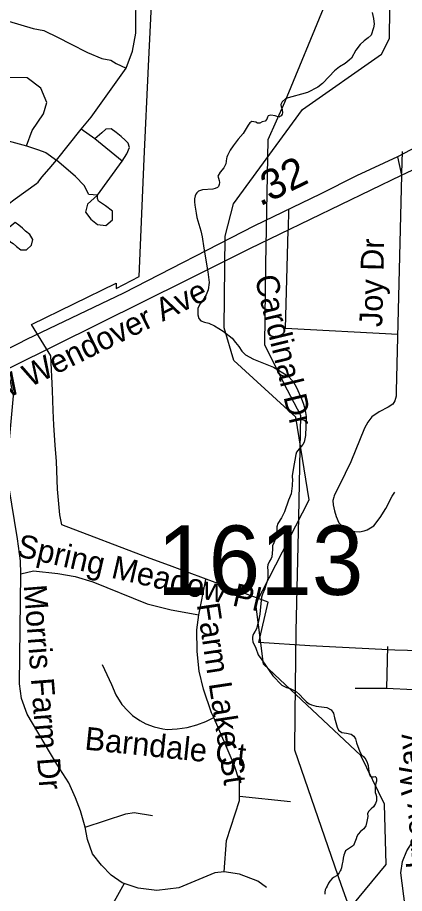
# Model space of a CAD drawing. Extents: x 1662474 to 1856135, y 779280 to 917889.
# Drawn here: x 1722010 to 1723616, y 832525 to 836159 of the extents above; entities that cross this region are included whole.
import ezdxf

# ---------------------------------------------------------------- set-up
doc = ezdxf.new("R2010")
doc.units = 0
for name, color, linetype in [('Cogo Default Point CELL', 7, 'Continuous'), ('Exist Boundary Political City Limit New', 7, 'Continuous'), ('Exist Hydrographic Creek Single Shore', 7, 'Continuous'), ('Exist Hydrographic Misc Water Feature', 7, 'Continuous'), ('Exist Road Non-System Type 51', 7, 'Continuous'), ('Exist Road Non-System Type 51 Label', 7, 'Continuous'), ('Exist Road Secondary Type 51 Attributed', 7, 'Continuous'), ('Exist Road Secondary Type 51 Divided Attributed', 7, 'Continuous'), ('Exist Road Secondary Type 51 Label', 7, 'Continuous'), ('Exist Utilities Electrical Transmission Line', 7, 'Continuous'), ('Map Preparation Boundary City Limit Buffer Line', 7, 'Continuous'), ('Prop DGN Element Guardrail', 7, 'Continuous')]:
    doc.layers.add(name, color=color, linetype=linetype)

msp = doc.modelspace()

# ---------------------------------------------------------------- linework, layer by layer
at = {"layer": 'Exist Boundary Political City Limit New'}
msp.add_lwpolyline([(1723786.9, 833529), (1723576.1, 833534.5), (1723223.9, 833552.5), (1723012.1, 833566.1), (1723050.6, 833733.9), (1722927.1, 833779.1), (1722781.8, 833832.9), (1722722.5, 833854.9), (1722652.1, 833880.9), (1722548.9, 833919.3), (1722193.4, 834054.1), (1722185.1, 834095.9), (1722176, 834201.7), (1722172, 834316.5), (1722165.9, 834384.5), (1722160.9, 834468.2), (1722158.5, 834528.1), (1722155.4, 834612.1), (1722148.5, 834756.2), (1722067.8, 834885.8), (1722418.8, 835056.8), (1722419.8, 835035.6), (1722515.2, 835085.2), (1722535.9, 835573.3), (1722554.2, 835957.6), (1722563.6, 836155.2), (1722573.2, 836360.9)], dxfattribs=at)
at = {"layer": 'Exist Hydrographic Creek Single Shore'}
for points in [[(1723482.5, 836180.6), (1723488.2, 836154.7), (1723490.4, 836131.1), (1723487.8, 836116.9), (1723478, 836085.6), (1723465.4, 836075.4), (1723449.1, 836062.2), (1723432.6, 836047.8), (1723414.2, 836023.9), (1723396.4, 835990.6), (1723387.2, 835981.9), (1723369.9, 835968.3), (1723346.5, 835954.1), (1723326, 835937.9), (1723303.5, 835914.5), (1723275.9, 835885.6), (1723256, 835869.6), (1723214, 835847.6), (1723124, 835823.7), (1723108.2, 835809.2), (1723102.4, 835798.5), (1723104.5, 835789.3), (1723107.1, 835783.6), (1723109, 835775.7), (1723110.2, 835764.4), (1723108, 835757.8), (1723103.8, 835751), (1723094.2, 835746), (1723079.4, 835751.5), (1723061, 835753.9), (1723050.8, 835750.8), (1723047.6, 835746), (1723045.2, 835737.3), (1723038.1, 835729.8), (1723025, 835726.1), (1723016.4, 835720.6), (1723006.1, 835721.1), (1722999, 835724.5), (1722982, 835728.4), (1722974.4, 835722.6), (1722967, 835712.4), (1722946.2, 835678.6), (1722925.5, 835654.7), (1722905, 835626.6), (1722892.8, 835609.2), (1722881.1, 835586.7), (1722878.8, 835580.1), (1722878, 835573.8), (1722875.1, 835551.8), (1722866.8, 835535.5), (1722850.8, 835517.1), (1722841.8, 835501.1), (1722843.6, 835492.8), (1722847.6, 835482.5), (1722848.4, 835474.9), (1722847.4, 835467), (1722843.9, 835457.8), (1722839.8, 835453.9), (1722830.8, 835449.2), (1722820, 835446.8), (1722777.5, 835443.6), (1722760.5, 835438.7), (1722754.6, 835432.1), (1722750.5, 835426.1), (1722747.9, 835419.8), (1722744.4, 835406.4), (1722743.9, 835394.1), (1722745.8, 835380.6), (1722748.1, 835364.4), (1722751, 835347.1), (1722754.6, 835329.2), (1722771.2, 835274.6), (1722775.9, 835248.9), (1722783.5, 835202.4), (1722799.8, 835104.6), (1722806.1, 835060.4), (1722801.1, 835029.8), (1722793, 835009), (1722780.1, 834988.2), (1722767.2, 834970.4), (1722758.9, 834952.6), (1722758.6, 834925), (1722762.5, 834910.9), (1722771.2, 834901.1), (1722785.9, 834895.4), (1722804, 834890.6)], [(1722804, 834890.6), (1722828.1, 834880.7), (1722863.9, 834858.1), (1722900.4, 834828.2), (1722914.5, 834811.4), (1722928.6, 834794.1), (1722941, 834775.4), (1722955.8, 834759.9), (1722990.1, 834742.4), (1723072, 834708.2), (1723132.4, 834672), (1723154.4, 834648.9), (1723168.2, 834624), (1723189.2, 834577), (1723196.1, 834558.9), (1723201.4, 834541.1), (1723204.8, 834520.8), (1723208.5, 834503.5), (1723206.6, 834462.6), (1723205.4, 834425.6), (1723199.8, 834396.9), (1723194.2, 834387.2), (1723179.4, 834370.2), (1723168.6, 834356.2), (1723165.6, 834346), (1723153.6, 834284.1), (1723150.2, 834257.6), (1723151, 834237.4), (1723150.5, 834225.6), (1723149.9, 834216.6), (1723145.2, 834182.8), (1723135, 834157.3), (1723117.9, 834109), (1723105.6, 834083.3), (1723090.4, 834059.4), (1723086.4, 834046.3), (1723085.9, 834033.7), (1723084.4, 834017.2), (1723083, 834002.8), (1723079.4, 833994.1), (1723073.5, 833979.6), (1723068.6, 833967.3), (1723068, 833952.6), (1723066.8, 833937.1), (1723064.9, 833921.1), (1723063.4, 833914.8), (1723056.2, 833903.2), (1723049.4, 833888.8), (1723047.9, 833878.3), (1723048.6, 833863.6), (1723048.9, 833850.8), (1723048.9, 833833.4), (1723045.8, 833820.3), (1723038.9, 833799.3), (1723036.2, 833789.1), (1723026.9, 833766.5), (1723022.9, 833754.7), (1723018.8, 833714), (1723016.1, 833683.8), (1723010, 833654.2), (1723002.1, 833622.4), (1722996.6, 833613.2), (1722989.6, 833601.9), (1722987.2, 833595.6), (1722985.1, 833588.1), (1722984.9, 833579.9), (1722987.2, 833569.4), (1722999.2, 833542.4), (1723009, 833514.8), (1723024.2, 833494.1), (1723069.4, 833427.9), (1723107.6, 833388.8), (1723126.6, 833379.1), (1723141.2, 833375.2), (1723152.9, 833370.2), (1723167.5, 833362.1), (1723180.6, 833350.2), (1723196.4, 833332.9), (1723209.5, 833320.1), (1723220, 833311.7), (1723229.8, 833307.2), (1723249.6, 833301.4), (1723293.5, 833296.4), (1723311.4, 833287.5), (1723321, 833272.3), (1723325.8, 833253.1), (1723336.5, 833215.3), (1723342.4, 833202.2), (1723355.5, 833192.2), (1723375.9, 833190.4), (1723394.8, 833185.4), (1723405.9, 833177.3), (1723412.9, 833166.8), (1723417.1, 833150.2), (1723430.2, 833112.2), (1723437.4, 833099.9), (1723447, 833091.4), (1723456.2, 833080.9), (1723460.8, 833068.6), (1723465.4, 833055.5)], [(1723465.4, 833055.5), (1723466.2, 833041.6), (1723469.1, 833022.4), (1723473.2, 833012.2), (1723476.4, 833009.8), (1723481.4, 833008.8), (1723488.2, 833009.3), (1723494.5, 833010.1), (1723499.2, 833006.7), (1723500.6, 832999.1), (1723499.8, 832991.4), (1723497.8, 832982.6), (1723494, 832968.4), (1723494.5, 832955.2), (1723494.8, 832944.5), (1723497.8, 832936.6), (1723499.5, 832927.7), (1723500.6, 832909.8), (1723496.4, 832898.8), (1723488.2, 832884.9), (1723477.5, 832876), (1723468.2, 832865.8), (1723462.5, 832856.1), (1723463.4, 832844.8), (1723460.1, 832824), (1723457.5, 832811.4), (1723456, 832805.6), (1723447.6, 832792.8), (1723433.9, 832781.8), (1723424.5, 832771.2), (1723419, 832761.6), (1723415, 832752.1), (1723410.2, 832737.9), (1723404, 832724.6), (1723391.9, 832715.1), (1723379.6, 832708), (1723371.2, 832701.7), (1723364.6, 832684.4), (1723361.5, 832671.2), (1723359.9, 832659.4), (1723357.8, 832647.4), (1723356.5, 832640.6), (1723355.1, 832631.1), (1723352.2, 832623.5), (1723349.6, 832618.8), (1723345, 832610.4), (1723339.8, 832603.6), (1723334.1, 832597.8), (1723324.2, 832592.2), (1723316.4, 832587), (1723306.1, 832576.2), (1723300.9, 832567.3), (1723295.6, 832555.8), (1723291.6, 832548.7), (1723287.5, 832540.6), (1723285.1, 832529.8), (1723284.9, 832522.2)]]:
    msp.add_lwpolyline(points, dxfattribs=at)
at = {"layer": 'Exist Hydrographic Misc Water Feature'}
for points in [[(1723220.4, 834158.6), (1723165.4, 834501.1), (1722908.3, 834736.1), (1722868.3, 834871.5), (1722872.4, 835252.2), (1722906.5, 835386.1), (1723193.3, 835777.4), (1723521.4, 836007), (1723554.4, 836072), (1723557.3, 836321.4), (1723582.3, 836373.4), (1723801.3, 836529.8)], [(1723368.8, 832438.2), (1723539.4, 832645.5), (1723533.3, 832895.1), (1723435.3, 833097.2), (1723030.3, 833476.4), (1722999.3, 833726.5), (1723220.4, 834158.6)]]:
    msp.add_lwpolyline(points, dxfattribs=at)
at = {"layer": 'Exist Road Non-System Type 51'}
for p, q in [((1722172, 835567.2), (1722274.1, 835695.6)), ((1722330.5, 835656.5), (1722274.1, 835695.6)), ((1722443.9, 835562.8), (1722330.5, 835656.5)), ((1723606.4, 835603.6), (1723604.2, 835512.2)), ((1722341.9, 835421.6), (1722443.9, 835562.8)), ((1723134.6, 835365.8), (1723132.9, 835277.2)), ((1722762, 833680.7), (1722791.4, 833827.4)), ((1723546, 833549.2), (1723540.8, 833377)), ((1723411.6, 833376.2), (1723540.8, 833377)), ((1722931.6, 832929.2), (1723143.6, 832905.9))]:
    msp.add_line(p, q, dxfattribs=at)
for points in [[(1722460.6, 835949.7), (1722487.8, 836019.2), (1722500.4, 836094.5), (1722500.4, 836180.9), (1722512.6, 836315.5), (1722511.6, 836333.9), (1722511.9, 836362), (1722513.6, 836390.1), (1722514.8, 836400.4), (1722516.1, 836413.7), (1722519.8, 836437.6), (1722530.5, 836482.4), (1722545.5, 836527.4), (1722569.9, 836582.4), (1722582.8, 836614.5), (1722623.4, 836730.9), (1722628.1, 836784.6), (1722630.5, 836824.4)], [(1721775.1, 836240.2), (1721797.1, 836234.2), (1721895.1, 836184), (1721933.5, 836161.2), (1721973, 836143.4), (1722075.1, 836114.2), (1722119, 836104.8), (1722179.4, 836076.9), (1722230.5, 836049.7), (1722300.4, 836014.2), (1722360.6, 835989.2), (1722397.1, 835981.9), (1722419, 835968.6), (1722460.6, 835949.7)], [(1722274.1, 835695.6), (1722315.9, 835745.4), (1722460.6, 835949.7)], [(1722047.1, 835626.5), (1722070.9, 835690.6), (1722117.9, 835759.9), (1722131.6, 835806.9), (1722107.4, 835866.4), (1722050.5, 835909.4), (1721970.9, 835910), (1721917.9, 835883), (1721874.9, 835830), (1721816.9, 835688.2)], [(1721816.9, 835688.2), (1721838.9, 835674.6), (1721877.2, 835663.4), (1721970.9, 835647.4), (1722047.1, 835626.5)], [(1722443.9, 835562.8), (1722463.6, 835594), (1722474.6, 835619.5), (1722469.9, 835637.9), (1722457.2, 835650.7), (1722439.9, 835665.9), (1722419.2, 835682.8), (1722398.8, 835697.2), (1722377, 835695.4), (1722360.6, 835680.7), (1722330.5, 835656.5)], [(1722047.1, 835626.5), (1722093, 835612.1), (1722127.4, 835599.8), (1722172, 835567.2)], [(1721941.9, 835362.2), (1722000.4, 835407.2), (1722088.9, 835470.9), (1722095.1, 835475.9), (1722110.6, 835496.4), (1722141.5, 835531), (1722172, 835567.2)], [(1722341.9, 835421.6), (1722306.4, 835425), (1722286.6, 835462.5), (1722250.1, 835499.8), (1722172, 835567.2)], [(1722341.9, 835421.6), (1722301.1, 835385.4), (1722292.8, 835352.2), (1722313.8, 835323.2), (1722342.4, 835299.9), (1722375.9, 835296.4), (1722404.5, 835320.5), (1722404.4, 835355.4), (1722375.4, 835377.8), (1722346.1, 835396.7), (1722342.4, 835408.4), (1722341.9, 835421.6)], [(1721999.6, 835309), (1721975.1, 835287.4), (1721966.5, 835277), (1721959.4, 835263.1), (1721962.2, 835249.2), (1721969.6, 835239.7), (1721978.6, 835230.2), (1721991.4, 835222.1), (1722006.1, 835208.8), (1722023.4, 835195.6), (1722047.4, 835195.4), (1722067.8, 835214.1), (1722073.4, 835238.7), (1722061, 835258.6), (1722043.1, 835273.2), (1722030.2, 835285.1), (1722014.9, 835297.4), (1721999.6, 835309)], [(1723588, 834844), (1723121.6, 834869.1), (1723132.9, 835277.2)], [(1722023.6, 833850.5), (1722021.9, 833904.6), (1722010.1, 833996.4), (1721974.6, 834216.4), (1721969.4, 834331.1), (1721993.2, 834589.6), (1721981.4, 834650.2), (1721962.9, 834694.4)], [(1722291.4, 832800.4), (1722271.4, 832867.6), (1722251, 832922.2), (1722223.6, 832983.6), (1722173, 833061.2), (1722049.4, 833268.9), (1722026.4, 833334.5), (1722018.6, 833394.4), (1722023.6, 833850.5)], [(1722023.6, 833850.5), (1722077, 833863.4), (1722177, 833852.1), (1722249.9, 833840.2), (1722322.6, 833818.4), (1722548.6, 833726.4), (1722647.6, 833701.4), (1722762, 833680.7)], [(1722824.8, 833254.4), (1722814.8, 833274.7), (1722782.5, 833372.5), (1722764.6, 833446.9), (1722756.2, 833528.4), (1722754.6, 833618.2), (1722762, 833680.7)], [(1722361.2, 833474.4), (1722400.6, 833391.4), (1722417.6, 833348.7), (1722442.6, 833309.6), (1722467.2, 833282), (1722487.9, 833263.6), (1722518.1, 833242.4), (1722542.6, 833229.2), (1722577.5, 833216.1), (1722613.1, 833208), (1722631.6, 833205.6), (1722672.8, 833208), (1722714, 833213.8), (1722753.9, 833224.2), (1722791.9, 833238.7), (1722824.8, 833254.4)], [(1723540.8, 833377), (1723654, 833370.7), (1723951.2, 833363.9)], [(1722931.6, 832929.2), (1722931.6, 832990.4), (1722909.2, 833058.1), (1722824.8, 833254.4)], [(1722867.9, 832614.9), (1722876.9, 832744.7), (1722931.6, 832910.9), (1722931.6, 832929.2)], [(1722291.4, 832800.4), (1722458.9, 832855), (1722494.2, 832861.5), (1722569.9, 832848.9)], [(1722453.1, 832566.8), (1722444.1, 832569.4), (1722398.8, 832601.2), (1722358.1, 832642.1), (1722321.4, 832689.9), (1722301.1, 832748.9), (1722291.4, 832800.4)], [(1723655.9, 832359.9), (1723618.9, 832470.4), (1723600.6, 832610.4), (1723607.6, 832657.1), (1723626, 832701.9), (1723652.5, 832743.7), (1723711.6, 832797.8)], [(1722867.9, 832614.9), (1722829.1, 832610.4), (1722679.1, 832548.9), (1722588.2, 832537.4), (1722510.4, 832546.6), (1722453.1, 832566.8)], [(1723043.4, 832549.2), (1723006.9, 832576.5), (1722931.6, 832605.4), (1722867.9, 832614.9)], [(1722453.1, 832566.8), (1722296.4, 832285.9)]]:
    msp.add_lwpolyline(points, dxfattribs=at)
at = {"layer": 'Exist Road Secondary Type 51 Attributed'}
for points in [[(1723587.1, 835581.7), (1723603.1, 835505.2)], [(1723603.1, 835505.2), (1723581.6, 834608.5), (1723581.1, 834588.8), (1723575.7, 834569.4), (1723567.1, 834554.6), (1723548.6, 834542.7), (1723511.1, 834522.8), (1723480.9, 834502.1), (1723463.7, 834480), (1723449.9, 834455), (1723393, 834316.4), (1723345.8, 834218.9), (1723331.4, 834190.2), (1723324.4, 834174.6)], [(1723324.4, 834174.6), (1723322.2, 834169.7), (1723319.1, 834155.3), (1723320.2, 834136.9), (1723325.3, 834112.2), (1723332.5, 834088.6), (1723343.8, 834063), (1723364.3, 834042.5), (1723388.9, 834031.2), (1723410.5, 834027.1), (1723429, 834026), (1723449.1, 834029.4), (1723461.2, 834033.6), (1723475.7, 834041.5), (1723488.5, 834050.7), (1723515.1, 834084.5), (1723538.8, 834122.5), (1723564.5, 834172.8), (1723575.8, 834190.2)]]:
    msp.add_lwpolyline(points, dxfattribs=at)
at = {"layer": 'Exist Road Secondary Type 51 Divided Attributed'}
for points in [[(1725218.9, 836394.1), (1724984, 836280.6), (1724710.5, 836144), (1724360.8, 835970.7), (1724000.8, 835783.5), (1723803, 835694), (1723587.1, 835581.7)], [(1723603.1, 835505.2), (1723822.3, 835607.3), (1724338.4, 835868.6), (1724756.8, 836081.4), (1725250.7, 836321.3)], [(1723587.1, 835581.7), (1723416.3, 835502.3), (1723265.7, 835425.8), (1722994.2, 835294.3), (1722449.4, 835015.7), (1722047.5, 834822.7), (1722013.1, 834805.3), (1721709.5, 834657.7), (1721555, 834587.5), (1721206.4, 834411.6)], [(1721243, 834339.3), (1721986.5, 834710.1), (1722714.7, 835070.5), (1722974.2, 835201.1), (1723603.1, 835505.2)]]:
    msp.add_lwpolyline(points, dxfattribs=at)
at = {"layer": 'Exist Utilities Electrical Transmission Line'}
msp.add_lwpolyline([(1723473.3, 839431), (1723445.1, 838486.9), (1723411.2, 837570.7), (1723389.1, 836806.6), (1723380.6, 836578.5), (1723373.2, 836450.5), (1723288.7, 836219.4), (1723118.2, 835806.8), (1723048.4, 835651.6), (1723038.9, 835135.3), (1723035.3, 834803.2), (1723115.6, 834640.3), (1723184.2, 834509.4), (1723175.6, 834085.4), (1723164.6, 833613.2), (1723161, 833269.1), (1723159.4, 833121.1), (1723353.4, 832558.7), (1723518.7, 832096.9), (1723561.3, 831968.3), (1723624.9, 831919.6)], dxfattribs=at)
at = {"layer": 'Map Preparation Boundary City Limit Buffer Line'}
msp.add_lwpolyline([(1723786.9, 833529), (1723576.1, 833534.5), (1723223.9, 833552.5), (1723012.1, 833566.1), (1723050.6, 833733.9), (1722927.1, 833779.1), (1722781.8, 833832.9), (1722722.5, 833854.9), (1722652.1, 833880.9), (1722548.9, 833919.3), (1722193.4, 834054.1), (1722185.1, 834095.9), (1722176, 834201.7), (1722172, 834316.5), (1722165.9, 834384.5), (1722160.9, 834468.2), (1722158.5, 834528.1), (1722155.4, 834612.1), (1722148.5, 834756.2), (1722067.8, 834885.8), (1722418.8, 835056.8), (1722419.8, 835035.6), (1722515.2, 835085.2), (1722535.9, 835573.3), (1722554.2, 835957.6), (1722563.6, 836155.2), (1722573.2, 836360.9)], dxfattribs=at)

# ---------------------------------------------------------------- texts
at = {"layer": 'Cogo Default Point CELL'}
msp.add_text('1613', height=288, dxfattribs=at).set_placement((1722588.9, 833763.7))
at = {"layer": 'Exist Road Non-System Type 51 Label'}
for s, rotation, p in [('Cardinal Dr', 283.5738, (1722994, 835080.1)), ('Spring Meadow Pl', 347.1106, (1722002.6, 833925.3)), ('Morris Farm Dr', 274.4396, (1722035.5, 833803.3)), ('Farm Lake St', 278.6108, (1722753.7, 833724.3)), ('Barndale Ct', 354.0825, (1722286, 833122.2)), ('Hackney Way', 94.7608, (1723741.7, 832409.9))]:
    msp.add_text(s, height=95, rotation=rotation, dxfattribs=at).set_placement(p)
at = {"layer": 'Exist Road Secondary Type 51 Label'}
for s, rotation, p in [('Joy Dr', 88.6532, (1723523.5, 834874.4)), ('W Wendover Ave', 26.3163, (1721922.1, 834555))]:
    msp.add_text(s, height=95, rotation=rotation, dxfattribs=at).set_placement(p)
at = {"layer": 'Prop DGN Element Guardrail'}
msp.add_text('.32', height=125, rotation=25.8432, dxfattribs=at).set_placement((1723016.2, 835374.4))

doc.saveas('drawing.dxf')
